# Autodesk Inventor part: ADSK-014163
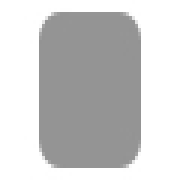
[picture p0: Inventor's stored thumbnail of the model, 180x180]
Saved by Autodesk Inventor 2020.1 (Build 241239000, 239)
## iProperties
Created: 2019-01
Part Number: ADSK-014163
Material: Stahl, weich
Document SubType Name: Modeling
Designer: lutzd
Language: de-DE
Size Designation: 5 x 39,384472 x 39,384472
Categories: <MemberInstance><Categories><Category DisplayName="Sonstige Bauteile" InternalName="5aa15e00-363f-49f2-933f-16f664388e3f" Mnemonic="OTHER"><Category DisplayName
Mass: 60.0398 g
Surface Area: 38.0412 cm^2
Volume: 7.64838 cm^3
Density: 7.85 g/cm^3
Appearance: Halbpoliert
IsCustomPart: 1
Title: end cap
Author: lutzd
Revision Number: -
Dimensions: 39,4x39,4x5 mm
Mass: 0,06 kg
DocNumber: ADSK-014163
Folder: 01 - Themengebiete\Simplification\01 - Packaging machine\
VDS_Category: 3D Komponenten
VDS_NumSchm: Autodesk
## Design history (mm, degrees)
sketch "Sketch1"
  geometry: L1 (0, 20.175)-(0, -21.446); L2 (-20.203, 0)-(20.169, 0); L3 (-19.692, 19.692)-(19.692, 19.692); L4 (19.692, 19.692)-(19.692, -19.692); L5 (19.692, -19.692)-(-19.692, -19.692); L6 (-19.692, -19.692)-(-19.692, 19.692); 1 further point
  constraints: 12 end point, 2 horizontal, 2 parallel, 2 point on line, 1 perpendicular, 1 vertical
  dimensions: "d0" = 39.38447 distance between parallel lines of L5 L3 (= height); "d1" = 19.69224 distance between parallel lines of L2 L3 (= 0.5 x height); "d2" = 39.38447 distance between parallel lines of L6 L4 (= width); "d3" = 19.69224 distance between parallel lines of L6 L1 (= 0.5 x width)
extrude "Extrusion1" new body sketch "Sketch1" distance "d4" = 5 (= thickness); taper "d5" = 0 deg
fillet "Fillet1" dims "d6" = 5 (= fillet), "d7" = 0, "fillet" = 5 [user parameter; used in 1 equation term]
chamfer "Chamfer1" distance "d8" = 0 (computed from chamfer); stored, may be unused: second distance "d9" = 2, angle "d10" = 45 deg; dims "d11" = 0, "chamfer" = 0 [user parameter; used in 1 equation term]
body "Solid1"
other parameters: "thickness" = 5 [user parameter; used in 1 equation term], "width" = 39.38447 [user parameter; used in 2 equation terms], "height" = 39.38447 [user parameter; used in 2 equation terms]
